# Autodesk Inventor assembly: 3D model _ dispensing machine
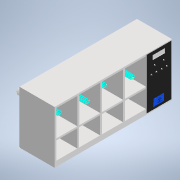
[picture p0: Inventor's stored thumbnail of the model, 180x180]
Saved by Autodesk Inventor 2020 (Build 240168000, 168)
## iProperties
Created: 2020-03
Part Number: 3D model _ dispensing machine
Document SubType Name: Assembly
Designer: Darugar
Author: Darugar
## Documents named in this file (5)
- C:\Users\Darugar\Desktop\Authentication part\3D model _ dispensing machine.iam
- C:\Users\Darugar\Desktop\Authentication part\Storing part.ipt
- C:\Users\Darugar\Downloads\DC Motor.ipt
- C:\Users\Darugar\Desktop\Authentication part\BURHAN.FINAL.iam
- C:\Users\Darugar\Desktop\Authentication part\spring coil.ipt
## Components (10 placed, 4 different names)
1. Storing part:1 — Rotational:1, Rotational:2, Rotational:3, Rotational:4, Rotational:5
2. DC Motor:1 — Rotational:1
3. DC Motor:2 — Rotational:2
4. DC Motor:3 — Rotational:4
5. DC Motor:4 — Rotational:3
6. BURHAN.FINAL:1 [sub-assembly] — Rotational:5
7. spring coil:1
8. spring coil:2
9. spring coil:3
10. spring coil:4
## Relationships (5: RevoluteJoint 5)
- Rotational:1 [RevoluteJoint]: Storing part:1 ↔ DC Motor:1
- Rotational:2 [RevoluteJoint]: Storing part:1 ↔ DC Motor:2
- Rotational:3 [RevoluteJoint]: Storing part:1 ↔ DC Motor:4
- Rotational:4 [RevoluteJoint]: Storing part:1 ↔ DC Motor:3
- Rotational:5 [RevoluteJoint]: Storing part:1 ↔ BURHAN.FINAL:1
